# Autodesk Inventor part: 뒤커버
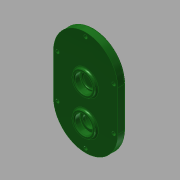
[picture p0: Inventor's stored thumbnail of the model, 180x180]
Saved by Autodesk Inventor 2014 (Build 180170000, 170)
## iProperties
Created: 2016-12
Part Number: 뒤커버
Material: Aluminum 6061
Document SubType Name: Modeling
Designer: mduedu
Density: 2.71 g/cm^3
Appearance: Smooth - Dark Forest Green
Mass: 236.429 g
Surface Area: 240.702 cm^2
Volume: 87.2434 cm^3
Author: mduedu
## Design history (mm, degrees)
sketch "스케치1"
  geometry: L1 (40, -25)-(40, 25); L2 (-40, 25)-(-40, -25); L3 (-40, -25)-(40, 25); L4 (40, -25)-(-40, 25); A1 r 40 centre (0, 25) between (40, 25) and (-40, 25); A2 r 40 centre (0, -25) between (-40, -25) and (40, -25); 1 further point
  constraints: 8 end point, 4 point on circle, 4 tangent, 2 centre point, 2 midpoint, 1 parallel, 1 vertical
  dimensions: "d0" = 130 dimension on A2 A1; "d2" = 80 distance between parallel lines of L1 L2
extrude "돌출1" new body sketch "스케치1" distance "d3" = 10; taper "d4" = 0 deg
sketch "스케치2"
  geometry: C1 r 14 at (0, 11); 1 further point
  constraints: 1 centre point, 1 vertical alignment
  dimensions: "d5" = 28 diameter of C1; "d6" = 11 distance of C1.centre point (0, 0)
extrude "돌출2" join sketch "스케치2" distance "d7" = 3; taper "d8" = 0 deg
sketch "스케치3"
  geometry: C1 r 14 at (0, -33.1); C2 r 14 at (0, 11) reference; 1 further point
  constraints: 1 centre point, 1 vertical alignment
  dimensions: "d9" = 28 diameter of C1; "d69" = 44.1 distance of C1.centre C2.centre
extrude "돌출3" join sketch "스케치3" distance "d11" = 3; taper "d12" = 0 deg
hole "구멍1" diameter "d15" = 22; stored, may be unused: countersink angle "d19" = 90 deg, drill point angle "d21" = 0 deg; dims "d13" = 10, "d14" = 10, "d16" = 6, "d17" = 4, "d18" = 2, "d20" = 7
hole "구멍2" diameter "d24" = 18; stored, may be unused: countersink angle "d28" = 90 deg, drill point angle "d30" = 0 deg; dims "d22" = 10, "d23" = 10, "d25" = 6, "d26" = 4, "d27" = 2, "d29" = 1
hole "구멍3" diameter "d33" = 22; stored, may be unused: countersink angle "d37" = 90 deg, drill point angle "d39" = 0 deg; dims "d31" = 10, "d32" = 10, "d34" = 6, "d35" = 4, "d36" = 2, "d38" = 7
sketch "스케치4"
  geometry: C1 r 14 at (0, -33.1) reference; C2 r 18 at (0, -33.1); 1 further point
  constraints: 1 centre point, 1 coincident
  dimensions: "d40" = 36 diameter of C2
extrude "돌출4" join sketch "스케치4" distance "d41" = 4; taper "d42" = 0 deg
hole "구멍4" diameter "d45" = 22; stored, may be unused: countersink angle "d49" = 90 deg, drill point angle "d51" = 0 deg; dims "d43" = 10, "d44" = 10, "d46" = 6, "d47" = 4, "d48" = 2, "d50" = 7
hole "구멍5" diameter "d54" = 15; stored, may be unused: countersink angle "d58" = 90 deg, drill point angle "d60" = 0 deg; dims "d52" = 10, "d53" = 10, "d55" = 6, "d56" = 4, "d57" = 2, "d59" = 7
fillet "모깎기1" dims "d61" = 0.3
fillet "모깎기2" dims "d62" = 2
chamfer "모따기1" distance "d63" = 1; stored, may be unused: second distance "d64" = 2, angle "d65" = 45 deg
fillet "모깎기3" dims "d66" = 2
fillet "모깎기4" dims "d67" = 2
fillet "모깎기5" dims "d68" = 2
sketch "스케치5"
  geometry: L1 (-40, 25)-(-40, -25) reference; L2 (40, -25)-(40, 25) reference; L3 (35, 25)-(35, -25); L4 (-35, -25)-(-35, 25); A1 r 40 centre (0, 25) between (40, 25) and (-40, 25) reference; A2 r 40 centre (0, -25) between (-40, -25) and (40, -25) reference; A3 r 35 centre (0, 25) between (35, 25) and (-35, 25); A4 r 35 centre (0, -25) between (-35, -25) and (35, -25); 2 further points
  constraints: 5 point on circle, 4 end point, 2 centre point, 1 vertical alignment, 3 other
  dimensions: "d70" = 5 distance between parallel lines of L2 L3
sketch "스케치6"
  geometry: 1 further point
hole "구멍6" sketch "스케치6" at (0, 60) diameter "d71" = 4.5; stored, may be unused: countersink angle "d75" = 90 deg, drill point angle "d77" = 0 deg; dims "d72" = 6, "d73" = 8, "d74" = 4.6, "d76" = 8
node "솔리드1"
pattern_linear "직사각형 패턴1"
